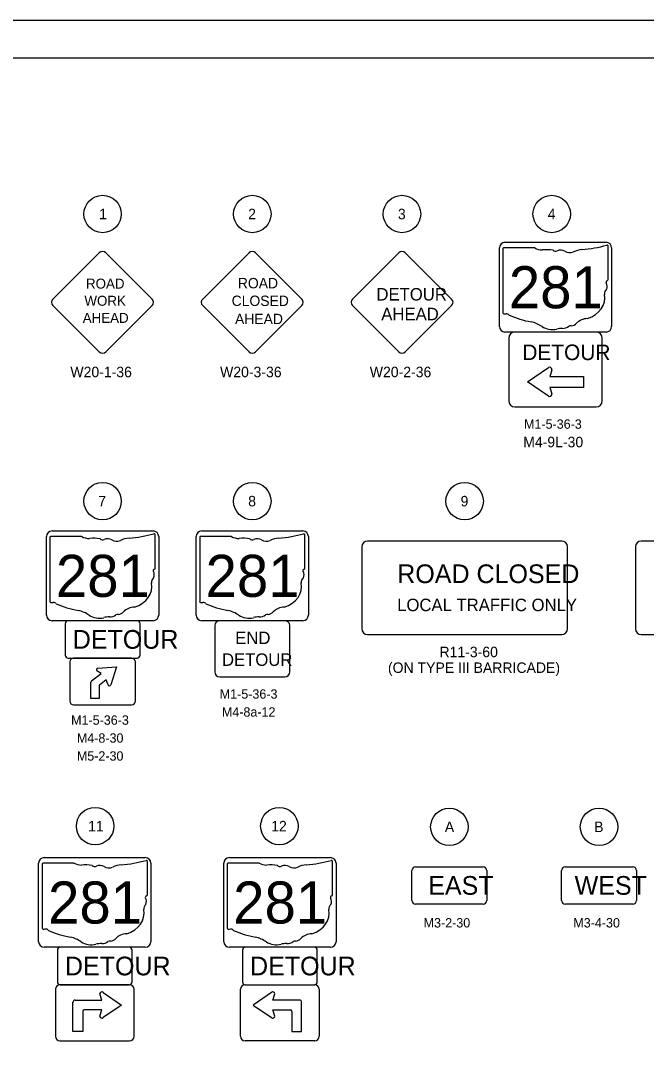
# Model space of a CAD drawing. Extents: x 0 to 680, y 0 to 834.
# Drawn here: x 381.5 to 548.7, y 165.9 to 440 of the extents above; entities that cross this region are included whole.
import ezdxf

# ---------------------------------------------------------------- set-up
doc = ezdxf.new("R2010")
doc.units = 0
for name, color, linetype in [('SH_Border', 7, 'Continuous'), ('SH_Cut_Line', 7, 'Continuous'), ('SH_Text', 7, 'Continuous'), ('SN_P_Signs', 7, 'Continuous'), ('SN_P_Text', 7, 'Continuous')]:
    doc.layers.add(name, color=color, linetype=linetype)

msp = doc.modelspace()

# ---------------------------------------------------------------- linework, layer by layer
at = {"layer": 'SH_Border'}
msp.add_lwpolyline([(30, 430), (670, 430), (670, 10), (30, 10)], close=True, dxfattribs=at)
at = {"layer": 'SH_Cut_Line'}
msp.add_lwpolyline([(0, 0), (680, 0), (680, 440), (0, 440)], close=True, dxfattribs=at)
at = {"layer": 'SH_Text'}
for centre in [(403.41, 388.25), (443.41, 388.25), (483.41, 388.25), (523.41, 388.25), (403.41, 311.46), (443.41, 311.46), (500.15, 311.46), (401.41, 224.55), (450.64, 224.55), (496.06, 224.35), (536.06, 224.35)]:
    msp.add_circle(centre, 5, dxfattribs=at)
at = {"layer": 'SN_P_Signs'}
for p, q in [((510.37, 378.92), (510.37, 361.84)), ((518.88, 379.21), (510.64, 379.21)), ((538.49, 370.7), (538.49, 379.63)), ((538.49, 370.7), (538.49, 370.7)), ((516.93, 343.35), (522.55, 347.16)), ((523.41, 346.51), (522.87, 344.81)), ((522.55, 339.55), (516.93, 343.35)), ((522.87, 344.81), (531.93, 344.81)), ((531.93, 344.81), (531.93, 341.89)), ((531.93, 341.89), (522.87, 341.89)), ((522.87, 341.89), (523.41, 340.19)), ((389.35, 301.73), (389.35, 284.65)), ((397.86, 302.02), (389.62, 302.02)), ((417.47, 293.51), (417.47, 302.45)), ((429.35, 301.73), (429.35, 284.65)), ((437.86, 302.02), (429.62, 302.02)), ((457.47, 293.51), (457.47, 302.45)), ((417.47, 293.51), (417.47, 293.51)), ((457.47, 293.51), (457.47, 293.51)), ((411.16, 269.49), (395.66, 269.49)), ((394.66, 268.49), (394.66, 257.99)), ((402.99, 265.36), (401.88, 266.11)), ((402.15, 266.83), (407.16, 267.14)), ((402.15, 266.83), (402.15, 266.83)), ((407.16, 267.14), (405.65, 262.35)), ((412.16, 257.99), (412.16, 268.49)), ((400.47, 263.38), (402.99, 265.36)), ((404.34, 263.64), (402.6, 262.27)), ((404.84, 262.47), (404.34, 263.64)), ((400.29, 258.71), (400.29, 263.01)), ((402.47, 262.02), (402.47, 258.71)), ((402.47, 258.71), (400.29, 258.71)), ((395.66, 256.99), (411.16, 256.99)), ((387.26, 214.37), (387.26, 197.3)), ((395.77, 214.67), (387.53, 214.67)), ((415.38, 206.16), (415.38, 215.09)), ((436.71, 214.37), (436.71, 197.3)), ((445.23, 214.67), (436.99, 214.67)), ((464.84, 206.16), (464.84, 215.09)), ((486.06, 204.69), (486.06, 212.69)), ((487.06, 213.69), (505.06, 213.69)), ((506.06, 212.69), (506.06, 204.69)), ((526.06, 204.69), (526.06, 212.69)), ((527.06, 213.69), (545.06, 213.69)), ((546.06, 212.69), (546.06, 204.69)), ((415.38, 206.16), (415.38, 206.16)), ((464.84, 206.16), (464.84, 206.16)), ((505.06, 203.69), (487.06, 203.69)), ((545.06, 203.69), (527.06, 203.69)), ((390.82, 180.94), (390.82, 168.34)), ((410.62, 182.14), (392.02, 182.14)), ((411.82, 168.34), (411.82, 180.94)), ((440.28, 168.34), (440.28, 180.94)), ((441.48, 182.14), (460.08, 182.14)), ((461.28, 180.94), (461.28, 168.34)), ((403.19, 178.01), (402.69, 179.7)), ((403.55, 180.06), (408.44, 176.7)), ((448.55, 180.06), (443.65, 176.7)), ((448.9, 178.01), (449.4, 179.7)), ((395.5, 169.58), (395.5, 177.45)), ((396.07, 178.01), (403.19, 178.01)), ((396.07, 178.01), (396.07, 178.01)), ((408.44, 176.7), (403.55, 173.35)), ((443.65, 176.7), (448.55, 173.35)), ((456.03, 178.01), (448.9, 178.01)), ((456.03, 178.01), (456.03, 178.01)), ((456.59, 169.58), (456.59, 177.45)), ((398.13, 175.01), (398.13, 169.58)), ((403.19, 175.39), (398.5, 175.39)), ((402.69, 173.7), (403.19, 175.39)), ((449.4, 173.7), (448.9, 175.39)), ((448.9, 175.39), (453.59, 175.39)), ((453.97, 175.01), (453.97, 169.58)), ((398.13, 169.58), (395.5, 169.58)), ((453.97, 169.58), (456.59, 169.58)), ((453.97, 169.58), (456.59, 169.58)), ((392.02, 167.14), (410.62, 167.14)), ((460.08, 167.14), (441.48, 167.14))]:
    msp.add_line(p, q, dxfattribs=at)
for points in [[(509.43, 358.18), (509.43, 379.18)], [(510.93, 380.68), (537.93, 380.68)], [(539.43, 379.18), (539.43, 358.18)], [(390.15, 365.51), (402.53, 377.89)], [(404.29, 377.89), (416.67, 365.51)], [(430.15, 365.51), (442.53, 377.89)], [(444.29, 377.89), (456.67, 365.51)], [(470.15, 365.51), (482.53, 377.89)], [(484.29, 377.89), (496.67, 365.51)], [(402.53, 351.37), (390.15, 363.74)], [(416.67, 363.74), (404.29, 351.37)], [(442.53, 351.37), (430.15, 363.74)], [(456.67, 363.74), (444.29, 351.37)], [(482.53, 351.37), (470.15, 363.74)], [(496.67, 363.74), (484.29, 351.37)], [(537.93, 356.68), (510.93, 356.68)], [(535.33, 356.68), (513.53, 356.68)], [(511.93, 355.08), (511.93, 338.28)], [(536.93, 338.28), (536.93, 355.08)], [(513.53, 336.68), (535.33, 336.68)], [(388.41, 280.99), (388.41, 301.99)], [(389.91, 303.49), (416.91, 303.49)], [(418.41, 301.99), (418.41, 280.99)], [(428.41, 280.99), (428.41, 301.99)], [(429.91, 303.49), (456.91, 303.49)], [(458.41, 301.99), (458.41, 280.99)], [(472.65, 299.23), (472.65, 277.35)], [(526.08, 300.79), (474.21, 300.79)], [(527.65, 277.35), (527.65, 299.23)], [(545.77, 299.23), (545.77, 277.35)], [(594.21, 300.79), (547.34, 300.79)], [(416.91, 279.49), (389.91, 279.49)], [(393.41, 278.69), (393.41, 270.29)], [(412.61, 279.49), (394.21, 279.49)], [(413.41, 270.29), (413.41, 278.69)], [(456.91, 279.49), (429.91, 279.49)], [(433.41, 278.19), (433.41, 265.79)], [(452.11, 279.49), (434.71, 279.49)], [(453.41, 265.79), (453.41, 278.19)], [(474.21, 275.79), (526.08, 275.79)], [(547.34, 275.79), (594.21, 275.79)], [(394.21, 269.49), (412.61, 269.49)], [(434.71, 264.49), (452.11, 264.49)], [(386.32, 193.64), (386.32, 214.64)], [(387.82, 216.14), (414.82, 216.14)], [(416.32, 214.64), (416.32, 193.64)], [(435.78, 193.64), (435.78, 214.64)], [(437.28, 216.14), (464.28, 216.14)], [(465.78, 214.64), (465.78, 193.64)], [(414.82, 192.14), (387.82, 192.14)], [(410.52, 192.14), (392.12, 192.14)], [(464.28, 192.14), (437.28, 192.14)], [(459.98, 192.14), (441.58, 192.14)], [(391.32, 191.34), (391.32, 182.94)], [(411.32, 182.94), (411.32, 191.34)], [(440.78, 191.34), (440.78, 182.94)], [(460.78, 182.94), (460.78, 191.34)], [(392.12, 182.14), (410.52, 182.14)], [(441.58, 182.14), (459.98, 182.14)]]:
    msp.add_lwpolyline(points, dxfattribs=at)
for centre, radius, start, end in [((510.93, 379.18), 1.5, 90, 180), ((537.93, 379.18), 1.5, 0, 90), ((403.41, 377), 1.25, 45, 135), ((443.41, 377), 1.25, 45, 135), ((483.41, 377), 1.25, 45, 135), ((391.04, 364.63), 1.25, 135, 225), ((415.79, 364.63), 1.25, 315, 45), ((431.04, 364.63), 1.25, 135, 225), ((455.79, 364.63), 1.25, 315, 45), ((471.04, 364.63), 1.25, 135, 225), ((495.79, 364.63), 1.25, 315, 45), ((510.93, 358.18), 1.5, 180, 270), ((513.53, 355.08), 1.6, 90, 180), ((535.33, 355.08), 1.6, 0, 90), ((537.93, 358.18), 1.5, 270, 0), ((403.41, 352.25), 1.25, 225, 315), ((443.41, 352.25), 1.25, 225, 315), ((483.41, 352.25), 1.25, 225, 315), ((522.87, 346.69), 0.572, 342.1992, 124.1969), ((522.87, 340.02), 0.572, 235.8031, 17.8008), ((513.53, 338.28), 1.6, 180, 270), ((535.33, 338.28), 1.6, 270, 0), ((389.91, 301.99), 1.5, 90, 180), ((416.91, 301.99), 1.5, 0, 90), ((429.91, 301.99), 1.5, 90, 180), ((456.91, 301.99), 1.5, 0, 90), ((474.21, 299.23), 1.56, 90, 180), ((526.08, 299.23), 1.56, 0, 90), ((547.34, 299.23), 1.56, 90, 180), ((389.91, 280.99), 1.5, 180, 270), ((416.91, 280.99), 1.5, 270, 0), ((429.91, 280.99), 1.5, 180, 270), ((456.91, 280.99), 1.5, 270, 0), ((394.21, 278.69), 0.8, 90, 180), ((412.61, 278.69), 0.8, 0, 90), ((434.71, 278.19), 1.3, 90, 180), ((452.11, 278.19), 1.3, 0, 90), ((474.21, 277.35), 1.56, 180, 270), ((526.08, 277.35), 1.56, 270, 0), ((547.34, 277.35), 1.56, 180, 270), ((394.21, 270.29), 0.8, 180, 270), ((395.66, 268.49), 1, 90, 180), ((411.16, 268.49), 1, 0, 90), ((412.61, 270.29), 0.8, 270, 0), ((402.18, 266.41), 0.417, 93.5999, 225.0001), ((400.76, 263.02), 0.468, 127.7857, 180), ((434.71, 265.79), 1.3, 180, 270), ((452.11, 265.79), 1.3, 270, 0), ((402.79, 262.02), 0.312, 127.3494, 180), ((405.25, 262.47), 0.417, 180.0509, 342.5804), ((395.66, 257.99), 1, 180, 270), ((411.16, 257.99), 1, 270, 360), ((387.82, 214.64), 1.5, 90, 180), ((414.82, 214.64), 1.5, 0, 90), ((437.28, 214.64), 1.5, 90, 180), ((464.28, 214.64), 1.5, 0, 90), ((487.06, 212.69), 1, 90, 180), ((505.06, 212.69), 1, 0, 90), ((527.06, 212.69), 1, 90, 180), ((545.06, 212.69), 1, 0, 90), ((487.06, 204.69), 1, 180, 270), ((505.06, 204.69), 1, 270, 0), ((527.06, 204.69), 1, 180, 270), ((545.06, 204.69), 1, 270, 0), ((387.82, 193.64), 1.5, 180, 270), ((392.12, 191.34), 0.8, 90, 180), ((410.52, 191.34), 0.8, 0, 90), ((414.82, 193.64), 1.5, 270, 0), ((437.28, 193.64), 1.5, 180, 270), ((441.58, 191.34), 0.8, 90, 180), ((459.98, 191.34), 0.8, 0, 90), ((464.28, 193.64), 1.5, 270, 0), ((392.02, 180.94), 1.2, 90, 180), ((392.12, 182.94), 0.8, 180, 270), ((410.52, 182.94), 0.8, 270, 0), ((410.62, 180.94), 1.2, 0, 90), ((441.48, 180.94), 1.2, 90, 180), ((441.58, 182.94), 0.8, 180, 270), ((459.98, 182.94), 0.8, 270, 0), ((460.08, 180.94), 1.2, 0, 90), ((403.19, 179.7), 0.5, 45.0001, 179.9983), ((448.9, 179.7), 0.5, 0.0017, 134.9999), ((396.07, 177.45), 0.563, 90, 180), ((456.03, 177.45), 0.563, 0, 90), ((398.51, 175.01), 0.374, 90, 180), ((403.19, 173.7), 0.5, 179.9983, 314.9999), ((448.9, 173.7), 0.5, 225.0001, 0.0017), ((453.59, 175.01), 0.374, 0, 90), ((392.02, 168.34), 1.2, 180, 270), ((410.62, 168.34), 1.2, 270, 0), ((441.48, 168.34), 1.2, 180, 270), ((460.08, 168.34), 1.2, 270, 360)]:
    msp.add_arc(centre, radius, start, end, dxfattribs=at)
for centre, major_axis, start_param, end_param in [((510.69, 378.95), (0.326, 0), 1.712693, 3.28349), ((520.84, 381.19), (3.16, 0), 4.042523, 4.731795), ((521.89, 369.62), (11.35, 0), 1.404758, 1.657858), ((524.47, 379.04), (0.912, 0), 3.836095, 5.185415), ((525.8, 377.07), (1.9, 0), 0.950623, 2.079405), ((528.25, 379.77), (2.28, 0), 4.081561, 5.145723), ((532.28, 373.99), (6, 0), 1.699011, 2.107814), ((528.47, 402.49), (29.83, 0), 4.814394, 5.042369), ((538.18, 379.67), (0.313, 0), 6.141152, 7.989035), ((538.42, 370.04), (0.485, 0), 1.883978, 3.671073), ((538.16, 370.67), (0.335, 0), 5.05454, 6.418171), ((539.61, 366.96), (2.12, 0), 2.387724, 3.262537), ((535.34, 368.91), (2.91, 0), 5.934695, 6.695948), ((530.14, 365.82), (7.46, 0), 5.101752, 6.440018), ((510.69, 361.8), (0.329, 0), 3.00124, 4.508301), ((510.74, 363.55), (2.51, 0), 4.665946, 4.897461), ((511.26, 360.85), (0.905, 0), 0.519207, 1.627899), ((522.68, 376.2), (21.54, 0), 4.195997, 4.488961), ((516.25, 354.17), (6.74, 0), 0.823519, 1.323587), ((533.29, 357.04), (4.09, 0), 1.647645, 2.488434), ((523.54, 360.77), (4.28, 0), 4.026481, 4.996735), ((526.01, 354.86), (3.51, 0), 1.495662, 1.94098), ((526.33, 359.49), (2.28, 0), 4.691044, 5.507374), ((528.39, 357.84), (0.641, 0), 1.147584, 2.315152), ((528.11, 360.18), (2.41, 0), 4.937069, 5.64225), ((389.67, 301.76), (0.326, 0), 1.712693, 3.28349), ((399.82, 304), (3.16, 0), 4.042523, 4.731795), ((400.87, 292.44), (11.35, 0), 1.404758, 1.657858), ((411.26, 296.81), (6, 0), 1.699011, 2.107814), ((407.45, 325.3), (29.83, 0), 4.814394, 5.042369), ((417.16, 302.48), (0.313, 0), 6.141152, 7.989035), ((429.67, 301.76), (0.326, 0), 1.712693, 3.28349), ((439.82, 304), (3.16, 0), 4.042523, 4.731795), ((440.87, 292.44), (11.35, 0), 1.404758, 1.657858), ((451.26, 296.81), (6, 0), 1.699011, 2.107814), ((447.45, 325.3), (29.83, 0), 4.814394, 5.042369), ((457.16, 302.48), (0.313, 0), 6.141152, 7.989035), ((403.45, 301.85), (0.912, 0), 3.836095, 5.185415), ((404.78, 299.88), (1.9, 0), 0.950623, 2.079405), ((407.23, 302.59), (2.28, 0), 4.081561, 5.145723), ((443.45, 301.85), (0.912, 0), 3.836095, 5.185415), ((444.78, 299.88), (1.9, 0), 0.950623, 2.079405), ((447.23, 302.59), (2.28, 0), 4.081561, 5.145723), ((417.14, 293.48), (0.335, 0), 5.05454, 6.418171), ((457.14, 293.48), (0.335, 0), 5.05454, 6.418171), ((418.59, 289.77), (2.12, 0), 2.387724, 3.262537), ((417.4, 292.86), (0.485, 0), 1.883978, 3.671073), ((414.32, 291.73), (2.91, 0), 5.934695, 6.695948), ((458.59, 289.77), (2.12, 0), 2.387724, 3.262537), ((457.4, 292.86), (0.485, 0), 1.883978, 3.671073), ((454.32, 291.73), (2.91, 0), 5.934695, 6.695948), ((409.12, 288.64), (7.46, 0), 5.101752, 6.440018), ((449.12, 288.64), (7.46, 0), 5.101752, 6.440018), ((389.67, 284.61), (0.329, 0), 3.00124, 4.508301), ((389.72, 286.36), (2.51, 0), 4.665946, 4.897461), ((390.24, 283.67), (0.905, 0), 0.519207, 1.627899), ((401.66, 299.01), (21.54, 0), 4.195997, 4.488961), ((412.27, 279.86), (4.09, 0), 1.647645, 2.488434), ((429.67, 284.61), (0.329, 0), 3.00124, 4.508301), ((429.72, 286.36), (2.51, 0), 4.665946, 4.897461), ((430.24, 283.67), (0.905, 0), 0.519207, 1.627899), ((441.66, 299.01), (21.54, 0), 4.195997, 4.488961), ((452.27, 279.86), (4.09, 0), 1.647645, 2.488434), ((395.23, 276.98), (6.74, 0), 0.823519, 1.323587), ((402.52, 283.58), (4.28, 0), 4.026481, 4.996735), ((404.99, 277.68), (3.51, 0), 1.495662, 1.94098), ((405.31, 282.3), (2.28, 0), 4.691044, 5.507374), ((407.37, 280.65), (0.641, 0), 1.147584, 2.315152), ((407.09, 283), (2.41, 0), 4.937069, 5.64225), ((435.23, 276.98), (6.74, 0), 0.823519, 1.323587), ((442.52, 283.58), (4.28, 0), 4.026481, 4.996735), ((444.99, 277.68), (3.51, 0), 1.495662, 1.94098), ((445.31, 282.3), (2.28, 0), 4.691044, 5.507374), ((447.37, 280.65), (0.641, 0), 1.147584, 2.315152), ((447.09, 283), (2.41, 0), 4.937069, 5.64225), ((387.58, 214.41), (0.326, 0), 1.712693, 3.28349), ((397.73, 216.65), (3.16, 0), 4.042523, 4.731795), ((398.78, 205.08), (11.35, 0), 1.404758, 1.657858), ((401.35, 214.5), (0.912, 0), 3.836095, 5.185415), ((402.69, 212.52), (1.9, 0), 0.950623, 2.079405), ((409.17, 209.45), (6, 0), 1.699011, 2.107814), ((405.36, 237.95), (29.83, 0), 4.814394, 5.042369), ((415.07, 215.13), (0.313, 0), 6.141152, 7.989035), ((437.04, 214.41), (0.326, 0), 1.712693, 3.28349), ((447.19, 216.65), (3.16, 0), 4.042523, 4.731795), ((448.24, 205.08), (11.35, 0), 1.404758, 1.657858), ((450.81, 214.5), (0.912, 0), 3.836095, 5.185415), ((452.15, 212.52), (1.9, 0), 0.950623, 2.079405), ((458.63, 209.45), (6, 0), 1.699011, 2.107814), ((454.82, 237.95), (29.83, 0), 4.814394, 5.042369), ((464.53, 215.13), (0.313, 0), 6.141152, 7.989035), ((405.14, 215.23), (2.28, 0), 4.081561, 5.145723), ((454.6, 215.23), (2.28, 0), 4.081561, 5.145723), ((415.31, 205.5), (0.485, 0), 1.883978, 3.671073), ((415.05, 206.12), (0.335, 0), 5.05454, 6.418171), ((464.77, 205.5), (0.485, 0), 1.883978, 3.671073), ((464.51, 206.12), (0.335, 0), 5.05454, 6.418171), ((416.5, 202.42), (2.12, 0), 2.387724, 3.262537), ((412.22, 204.37), (2.91, 0), 5.934695, 6.695948), ((465.96, 202.42), (2.12, 0), 2.387724, 3.262537), ((461.68, 204.37), (2.91, 0), 5.934695, 6.695948), ((407.03, 201.28), (7.46, 0), 5.101752, 6.440018), ((456.49, 201.28), (7.46, 0), 5.101752, 6.440018), ((387.58, 197.26), (0.329, 0), 3.00124, 4.508301), ((387.63, 199.01), (2.51, 0), 4.665946, 4.897461), ((388.14, 196.31), (0.905, 0), 0.519207, 1.627899), ((399.56, 211.65), (21.54, 0), 4.195997, 4.488961), ((393.14, 189.62), (6.74, 0), 0.823519, 1.323587), ((410.18, 192.5), (4.09, 0), 1.647645, 2.488434), ((437.04, 197.26), (0.329, 0), 3.00124, 4.508301), ((437.09, 199.01), (2.51, 0), 4.665946, 4.897461), ((437.6, 196.31), (0.905, 0), 0.519207, 1.627899), ((449.02, 211.65), (21.54, 0), 4.195997, 4.488961), ((442.6, 189.62), (6.74, 0), 0.823519, 1.323587), ((459.64, 192.5), (4.09, 0), 1.647645, 2.488434), ((400.43, 196.23), (4.28, 0), 4.026481, 4.996735), ((402.9, 190.32), (3.51, 0), 1.495662, 1.94098), ((403.21, 194.95), (2.28, 0), 4.691044, 5.507374), ((405.27, 193.29), (0.641, 0), 1.147584, 2.315152), ((405, 195.64), (2.41, 0), 4.937069, 5.64225), ((449.89, 196.23), (4.28, 0), 4.026481, 4.996735), ((452.36, 190.32), (3.51, 0), 1.495662, 1.94098), ((452.67, 194.95), (2.28, 0), 4.691044, 5.507374), ((454.73, 193.29), (0.641, 0), 1.147584, 2.315152), ((454.46, 195.64), (2.41, 0), 4.937069, 5.64225)]:
    msp.add_ellipse(centre, major_axis=major_axis, ratio=0.8, start_param=start_param, end_param=end_param, dxfattribs=at)

# ---------------------------------------------------------------- texts
at = {"layer": 'SH_Text'}
for s, p in [('1', (402.47, 386.85)), ('2', (442.31, 386.85)), ('3', (482.32, 386.85)), ('4', (522.35, 386.85)), ('7', (402.25, 310.06)), ('8', (442.31, 310.06)), ('9', (499.07, 310.06)), ('11', (399.53, 223.15)), ('12', (448.46, 223.15)), ('A', (494.86, 222.95)), ('B', (534.76, 222.95))]:
    msp.add_text(s, height=2.8, dxfattribs=at).set_placement(p)
at = {"layer": 'SN_P_Signs'}
for s, height, p in [('281', 11.25, (511.96, 363.04)), ('ROAD', 2.665, (398.97, 368.3)), ('ROAD', 2.778, (439.56, 368.37)), ('DETOUR', 3.333, (476.58, 365.11)), ('WORK', 2.665, (398.55, 363.71)), ('CLOSED', 2.778, (437.9, 363.65)), ('AHEAD', 3.333, (477.88, 359.84)), ('AHEAD', 2.665, (398.1, 359.13)), ('AHEAD', 2.778, (438.8, 358.79)), ('DETOUR', 4.167, (515.58, 349.18)), ('281', 11.25, (390.94, 285.86)), ('281', 11.25, (430.94, 285.86)), ('ROAD CLOSED', 5, (482.14, 289.54)), ('LOCAL TRAFFIC ONLY', 3.3333, (482.12, 282.04)), ('DETOUR', 5, (395.44, 271.99)), ('END', 3.333, (438.85, 273.22)), ('DETOUR', 3.333, (435.31, 267.4)), ('EAST', 5, (490.42, 206.19)), ('WEST', 5, (529.54, 206.19)), ('281', 11.25, (388.85, 198.5)), ('281', 11.25, (438.31, 198.5)), ('DETOUR', 5, (393.35, 184.64)), ('DETOUR', 5, (442.81, 184.64))]:
    msp.add_text(s, height=height, dxfattribs=at).set_placement(p)
at = {"layer": 'SN_P_Text'}
for s, height, p in [('W20-1-36', 2.8, (394.8, 344.6)), ('W20-3-36', 2.8, (434.8, 344.6)), ('W20-2-36', 2.8, (474.8, 344.6)), ('M1-5-36-3', 2.5, (516.02, 330.82)), ('M4-9L-30', 2.8, (515.8, 325.87)), ('R11-3-60 ', 2.8, (493.43, 269.72)), ('(ON TYPE III BARRICADE)', 2.8, (479.66, 265.52)), ('M1-5-36-3', 2.5, (434.71, 258.63)), ('M4-8a-12', 2.5, (435.29, 253.83)), ('M1-5-36-3', 2.5, (395, 251.66)), ('M4-8-30', 2.5, (396.53, 246.86)), ('M5-2-30', 2.5, (396.53, 242.06)), ('M3-2-30', 2.5, (489.19, 197.44)), ('M3-4-30', 2.5, (529.19, 197.44))]:
    msp.add_text(s, height=height, dxfattribs=at).set_placement(p)

doc.saveas('drawing.dxf')
